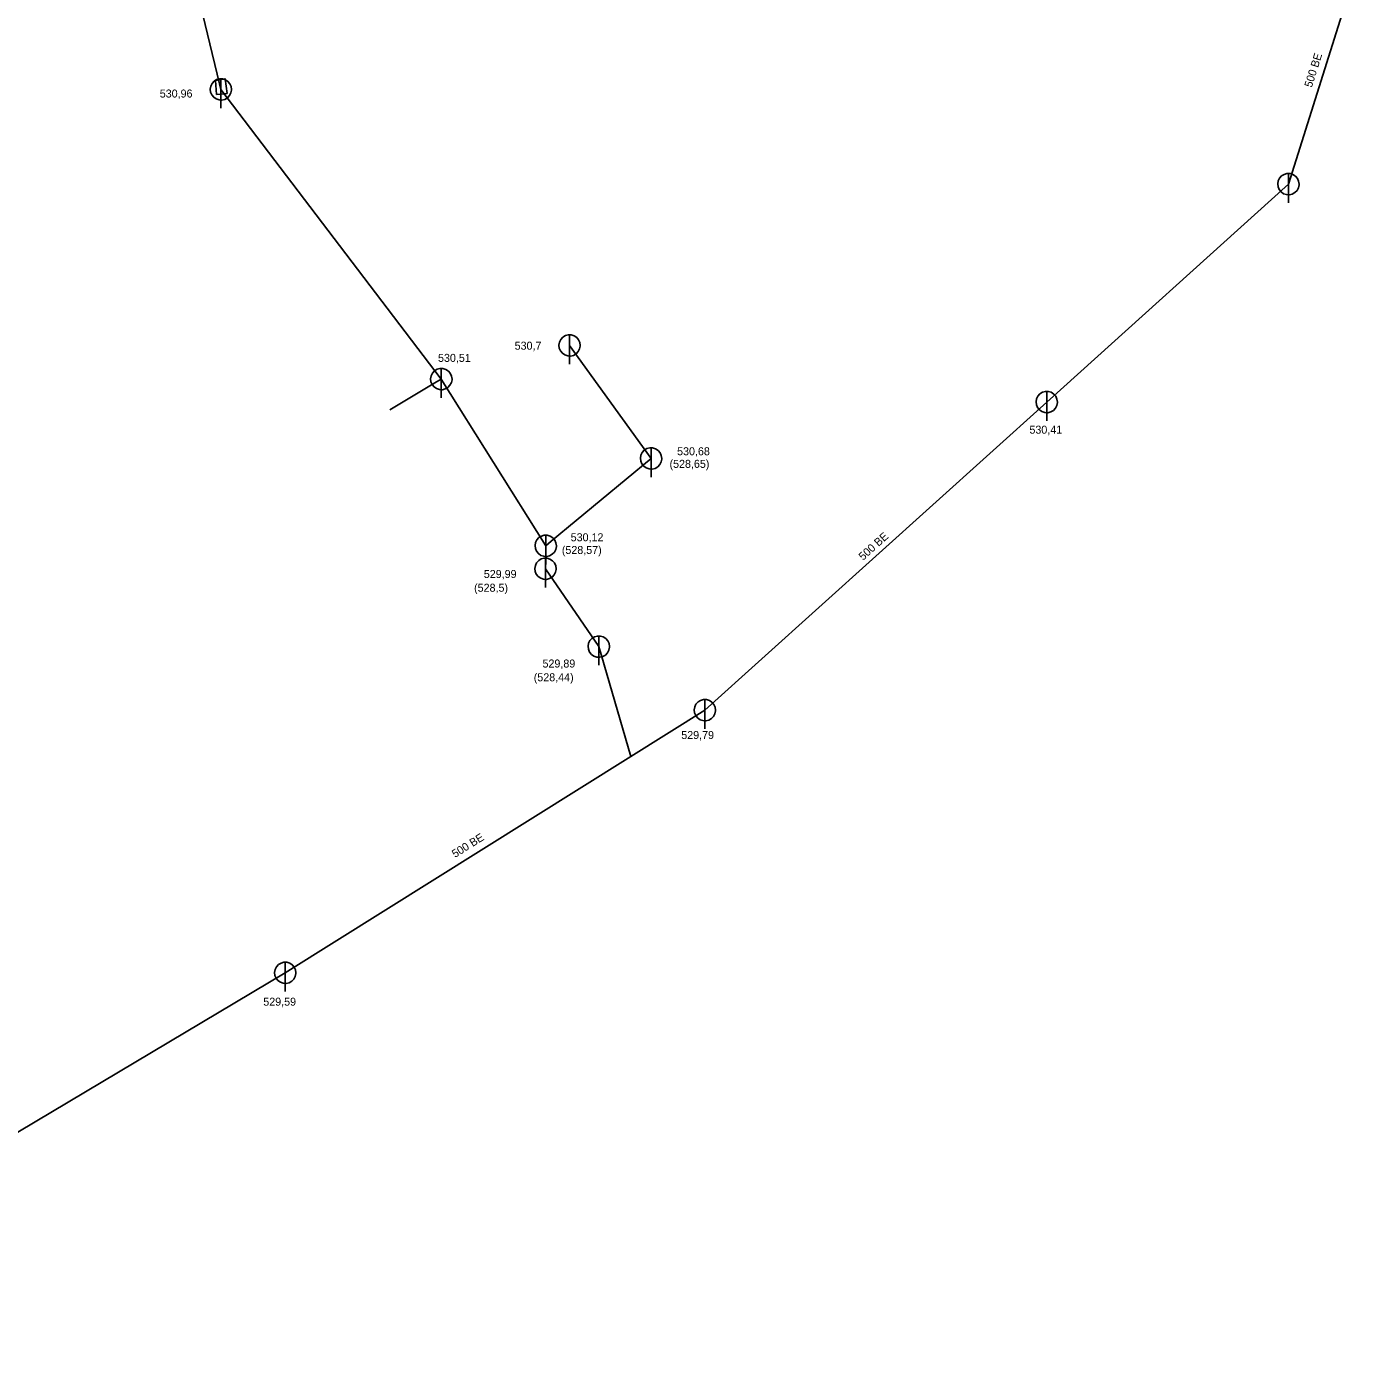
# Model space of a CAD drawing. Extents: x -476058 to -471893, y -1155786 to -1152000.
# Drawn here: x -473300 to -473175.2, y -1153991 to -1153865.1 of the extents above; entities that cross this region are included whole.
import ezdxf

# ---------------------------------------------------------------- set-up
doc = ezdxf.new("R2010")
doc.units = 0
for name, color, linetype in [('Vrstva 10', 7, 'Continuous'), ('Vrstva 18', 7, 'Continuous'), ('Vrstva 22', 7, 'Continuous'), ('Vrstva 3', 7, 'Continuous'), ('Vrstva 4', 7, 'Continuous'), ('Vrstva 45', 7, 'Continuous'), ('Vrstva 46', 7, 'Continuous'), ('Vrstva 50', 7, 'Continuous'), ('Vrstva 51', 7, 'Continuous')]:
    doc.layers.add(name, color=color, linetype=linetype)

msp = doc.modelspace()

# ---------------------------------------------------------------- linework, layer by layer
at = {"layer": 'Vrstva 10'}
for p, q in [((-473281.84, -1153869.96), (-473281.84, -1153872.71)), ((-473181.83, -1153878.84), (-473181.83, -1153881.58)), ((-473249.17, -1153893.95), (-473249.17, -1153896.7)), ((-473261.19, -1153897.1), (-473261.19, -1153899.85)), ((-473204.47, -1153899.25), (-473204.47, -1153902)), ((-473241.54, -1153904.54), (-473241.54, -1153907.29)), ((-473251.41, -1153912.73), (-473251.41, -1153915.48)), ((-473251.43, -1153914.87), (-473251.43, -1153917.62)), ((-473246.44, -1153922.17), (-473246.44, -1153924.92)), ((-473236.5, -1153928.13), (-473236.5, -1153930.88)), ((-473275.82, -1153952.74), (-473275.82, -1153955.49))]:
    msp.add_line(p, q, dxfattribs=at)
for points in [[(-473280.84, -1153870.96), (-473280.88, -1153870.68), (-473281, -1153870.42), (-473281.18, -1153870.21), (-473281.42, -1153870.05), (-473281.68, -1153869.97), (-473281.97, -1153869.97), (-473282.24, -1153870.04), (-473282.48, -1153870.19), (-473282.67, -1153870.4), (-473282.79, -1153870.65), (-473282.84, -1153870.93), (-473282.81, -1153871.21), (-473282.7, -1153871.47), (-473282.52, -1153871.69), (-473282.29, -1153871.85), (-473282.02, -1153871.94), (-473281.74, -1153871.96), (-473281.47, -1153871.89), (-473281.22, -1153871.75), (-473281.03, -1153871.54), (-473280.9, -1153871.29), (-473280.84, -1153871.02), (-473280.84, -1153870.96)], [(-473180.83, -1153879.84), (-473180.87, -1153879.56), (-473180.98, -1153879.3), (-473181.17, -1153879.08), (-473181.4, -1153878.93), (-473181.67, -1153878.85), (-473181.96, -1153878.84), (-473182.23, -1153878.92), (-473182.47, -1153879.07), (-473182.66, -1153879.28), (-473182.78, -1153879.53), (-473182.83, -1153879.81), (-473182.8, -1153880.09), (-473182.69, -1153880.35), (-473182.51, -1153880.57), (-473182.28, -1153880.73), (-473182.01, -1153880.82), (-473181.73, -1153880.83), (-473181.46, -1153880.76), (-473181.21, -1153880.62), (-473181.02, -1153880.42), (-473180.89, -1153880.17), (-473180.83, -1153879.89), (-473180.83, -1153879.84)], [(-473248.17, -1153894.95), (-473248.21, -1153894.67), (-473248.33, -1153894.41), (-473248.51, -1153894.2), (-473248.74, -1153894.04), (-473249.02, -1153893.96), (-473249.3, -1153893.96), (-473249.57, -1153894.03), (-473249.81, -1153894.18), (-473250, -1153894.39), (-473250.12, -1153894.64), (-473250.17, -1153894.92), (-473250.14, -1153895.2), (-473250.03, -1153895.46), (-473249.85, -1153895.68), (-473249.62, -1153895.84), (-473249.35, -1153895.93), (-473249.07, -1153895.95), (-473248.8, -1153895.88), (-473248.55, -1153895.74), (-473248.36, -1153895.53), (-473248.23, -1153895.28), (-473248.17, -1153895.01), (-473248.17, -1153894.95)], [(-473260.19, -1153898.1), (-473260.23, -1153897.82), (-473260.35, -1153897.56), (-473260.53, -1153897.35), (-473260.77, -1153897.2), (-473261.04, -1153897.11), (-473261.32, -1153897.11), (-473261.59, -1153897.18), (-473261.83, -1153897.33), (-473262.02, -1153897.54), (-473262.14, -1153897.79), (-473262.19, -1153898.07), (-473262.16, -1153898.35), (-473262.05, -1153898.61), (-473261.87, -1153898.83), (-473261.64, -1153898.99), (-473261.37, -1153899.08), (-473261.09, -1153899.1), (-473260.82, -1153899.03), (-473260.57, -1153898.89), (-473260.38, -1153898.68), (-473260.25, -1153898.43), (-473260.19, -1153898.16), (-473260.19, -1153898.1)], [(-473203.47, -1153900.25), (-473203.51, -1153899.97), (-473203.63, -1153899.71), (-473203.81, -1153899.5), (-473204.04, -1153899.34), (-473204.32, -1153899.26), (-473204.6, -1153899.26), (-473204.87, -1153899.33), (-473205.11, -1153899.48), (-473205.3, -1153899.69), (-473205.42, -1153899.94), (-473205.47, -1153900.22), (-473205.44, -1153900.5), (-473205.33, -1153900.76), (-473205.15, -1153900.98), (-473204.92, -1153901.14), (-473204.65, -1153901.23), (-473204.37, -1153901.25), (-473204.1, -1153901.18), (-473203.85, -1153901.04), (-473203.66, -1153900.83), (-473203.53, -1153900.58), (-473203.47, -1153900.31), (-473203.47, -1153900.25)], [(-473240.54, -1153905.54), (-473240.58, -1153905.26), (-473240.7, -1153905), (-473240.88, -1153904.79), (-473241.11, -1153904.64), (-473241.39, -1153904.55), (-473241.67, -1153904.55), (-473241.94, -1153904.62), (-473242.18, -1153904.77), (-473242.37, -1153904.98), (-473242.49, -1153905.23), (-473242.54, -1153905.51), (-473242.51, -1153905.79), (-473242.4, -1153906.05), (-473242.22, -1153906.27), (-473241.99, -1153906.43), (-473241.72, -1153906.52), (-473241.44, -1153906.54), (-473241.17, -1153906.47), (-473240.92, -1153906.33), (-473240.73, -1153906.12), (-473240.6, -1153905.87), (-473240.54, -1153905.6), (-473240.54, -1153905.54)], [(-473250.41, -1153913.73), (-473250.45, -1153913.45), (-473250.57, -1153913.19), (-473250.75, -1153912.98), (-473250.98, -1153912.82), (-473251.26, -1153912.74), (-473251.54, -1153912.74), (-473251.81, -1153912.81), (-473252.05, -1153912.96), (-473252.24, -1153913.17), (-473252.36, -1153913.42), (-473252.41, -1153913.7), (-473252.38, -1153913.98), (-473252.27, -1153914.24), (-473252.09, -1153914.46), (-473251.86, -1153914.62), (-473251.59, -1153914.71), (-473251.31, -1153914.73), (-473251.04, -1153914.66), (-473250.79, -1153914.52), (-473250.6, -1153914.31), (-473250.47, -1153914.06), (-473250.41, -1153913.79), (-473250.41, -1153913.73)], [(-473250.43, -1153915.87), (-473250.47, -1153915.59), (-473250.59, -1153915.33), (-473250.77, -1153915.12), (-473251.01, -1153914.97), (-473251.28, -1153914.88), (-473251.56, -1153914.88), (-473251.83, -1153914.95), (-473252.07, -1153915.1), (-473252.26, -1153915.31), (-473252.38, -1153915.56), (-473252.43, -1153915.84), (-473252.4, -1153916.12), (-473252.29, -1153916.38), (-473252.11, -1153916.6), (-473251.88, -1153916.76), (-473251.61, -1153916.85), (-473251.33, -1153916.87), (-473251.06, -1153916.8), (-473250.81, -1153916.66), (-473250.62, -1153916.45), (-473250.49, -1153916.2), (-473250.43, -1153915.93), (-473250.43, -1153915.87)], [(-473245.44, -1153923.17), (-473245.48, -1153922.89), (-473245.6, -1153922.63), (-473245.78, -1153922.42), (-473246.02, -1153922.27), (-473246.29, -1153922.18), (-473246.57, -1153922.18), (-473246.84, -1153922.25), (-473247.08, -1153922.4), (-473247.27, -1153922.61), (-473247.39, -1153922.86), (-473247.44, -1153923.14), (-473247.41, -1153923.42), (-473247.3, -1153923.68), (-473247.12, -1153923.9), (-473246.89, -1153924.06), (-473246.62, -1153924.15), (-473246.34, -1153924.17), (-473246.07, -1153924.1), (-473245.82, -1153923.96), (-473245.63, -1153923.75), (-473245.5, -1153923.5), (-473245.44, -1153923.23), (-473245.44, -1153923.17)], [(-473235.5, -1153929.13), (-473235.54, -1153928.85), (-473235.66, -1153928.59), (-473235.84, -1153928.38), (-473236.08, -1153928.23), (-473236.35, -1153928.14), (-473236.63, -1153928.14), (-473236.9, -1153928.21), (-473237.14, -1153928.36), (-473237.33, -1153928.57), (-473237.45, -1153928.82), (-473237.5, -1153929.1), (-473237.47, -1153929.38), (-473237.36, -1153929.64), (-473237.18, -1153929.86), (-473236.95, -1153930.02), (-473236.68, -1153930.11), (-473236.4, -1153930.13), (-473236.13, -1153930.06), (-473235.88, -1153929.92), (-473235.69, -1153929.71), (-473235.56, -1153929.46), (-473235.5, -1153929.19), (-473235.5, -1153929.13)], [(-473274.82, -1153953.74), (-473274.85, -1153953.46), (-473274.97, -1153953.2), (-473275.15, -1153952.99), (-473275.39, -1153952.83), (-473275.66, -1153952.75), (-473275.94, -1153952.75), (-473276.21, -1153952.82), (-473276.45, -1153952.97), (-473276.64, -1153953.18), (-473276.77, -1153953.43), (-473276.82, -1153953.71), (-473276.78, -1153953.99), (-473276.67, -1153954.25), (-473276.5, -1153954.47), (-473276.27, -1153954.63), (-473276, -1153954.72), (-473275.72, -1153954.73), (-473275.44, -1153954.67), (-473275.2, -1153954.53), (-473275, -1153954.32), (-473274.87, -1153954.07), (-473274.82, -1153953.79), (-473274.82, -1153953.74)]]:
    msp.add_lwpolyline(points, dxfattribs=at)
at = {"layer": 'Vrstva 22'}
msp.add_lwpolyline([(-473282.35, -1153870.13), (-473281.45, -1153869.96), (-473281.26, -1153871.33), (-473282.24, -1153871.43)], close=True, dxfattribs=at)
at = {"layer": 'Vrstva 45'}
for points in [[(-473281.84, -1153870.96), (-473261.19, -1153898.1)], [(-473261.19, -1153898.1), (-473251.41, -1153913.73)], [(-473204.47, -1153900.25), (-473236.5, -1153929.13)], [(-473251.41, -1153913.73), (-473251.43, -1153915.87)], [(-473251.43, -1153915.87), (-473246.44, -1153923.17)], [(-473246.44, -1153923.17), (-473243.43, -1153933.47)], [(-473236.5, -1153929.13), (-473243.43, -1153933.47)], [(-473243.43, -1153933.47), (-473275.82, -1153953.74)], [(-473275.82, -1153953.74), (-473338.32, -1153990.97)]]:
    msp.add_lwpolyline(points, dxfattribs=at)
at = {"layer": 'Vrstva 46'}
for points in [[(-473175.2, -1153858.78), (-473181.83, -1153879.84)], [(-473181.83, -1153879.84), (-473204.47, -1153900.25)]]:
    msp.add_lwpolyline(points, dxfattribs=at)
at = {"layer": 'Vrstva 50'}
msp.add_lwpolyline([(-473249.17, -1153894.95), (-473241.54, -1153905.54), (-473250.89, -1153913.3), (-473251.41, -1153913.73)], dxfattribs=at)
at = {"layer": 'Vrstva 51'}
for points in [[(-473284.45, -1153860.2), (-473281.97, -1153870.42), (-473281.84, -1153870.96)], [(-473266.03, -1153900.98), (-473261.8, -1153898.46), (-473261.19, -1153898.1)]]:
    msp.add_lwpolyline(points, dxfattribs=at)

# ---------------------------------------------------------------- texts
at = {"layer": 'Vrstva 18'}
for rotation, p in [(72.5246, (-473179.64, -1153870.83)), (42.0395, (-473221.68, -1153915.14)), (32.0435, (-473259.91, -1153942.99))]:
    msp.add_text('500 BE', height=0.75, rotation=rotation, dxfattribs=at).set_placement(p)
at = {"layer": 'Vrstva 3'}
for s, p in [('530,96', (-473287.57, -1153871.72)), ('530,7', (-473254.32, -1153895.35)), ('530,51', (-473261.5, -1153896.49)), ('530,41', (-473206.09, -1153903.22)), ('530,68', (-473239.1, -1153905.24)), ('530,12', (-473249.07, -1153913.3)), ('529,99', (-473257.21, -1153916.74)), ('529,89', (-473251.71, -1153925.13)), ('529,79', (-473238.71, -1153931.83)), ('529,59', (-473277.87, -1153956.82))]:
    msp.add_text(s, height=0.75, dxfattribs=at).set_placement(p)
at = {"layer": 'Vrstva 4'}
for s, p in [('(528,65)', (-473239.81, -1153906.42)), ('(528,57)', (-473249.9, -1153914.49)), ('(528,5)', (-473258.12, -1153918.03)), ('(528,44)', (-473252.53, -1153926.42))]:
    msp.add_text(s, height=0.75, dxfattribs=at).set_placement(p)

doc.saveas('drawing.dxf')
